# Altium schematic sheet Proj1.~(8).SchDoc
size A4
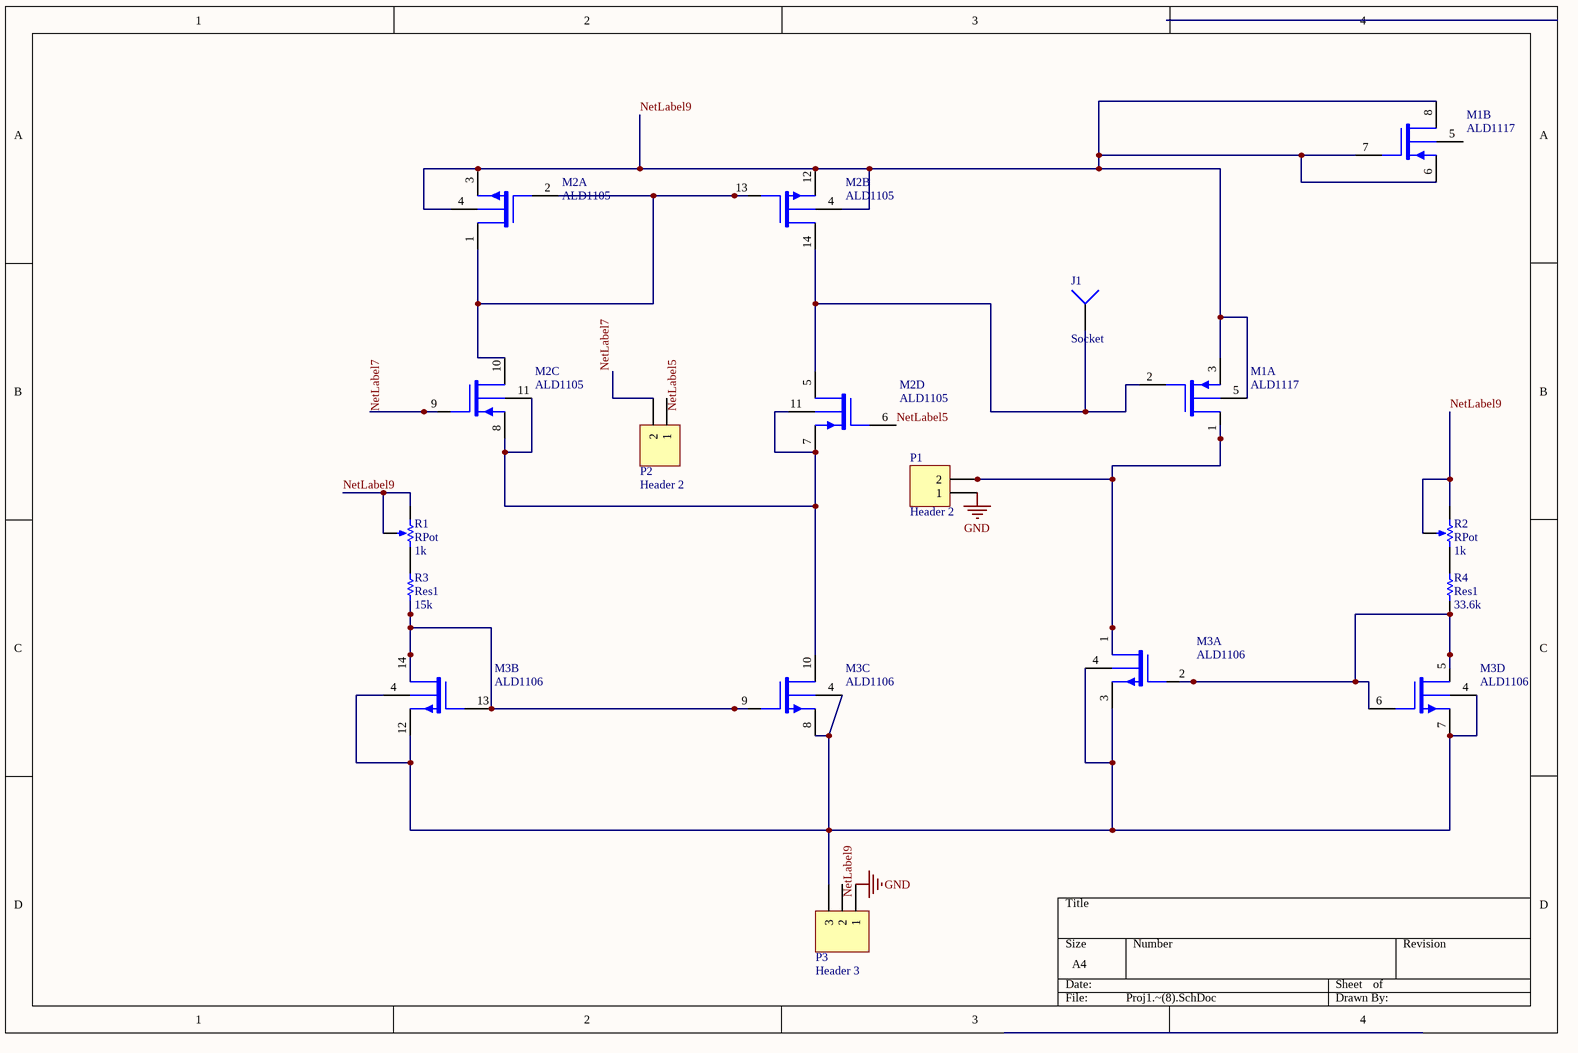
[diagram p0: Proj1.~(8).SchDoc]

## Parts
J1  Socket  [PIN1]
M1  ALD1117  [DIP-8]  (parts A,B of 2)
M2  ALD1105  [DIP-14]  (parts A,B,C,D of 4)
M3  ALD1106  [DIP-14]  (parts A,B,C,D of 4)
P1  Header 2  [HDR1X2]
P2  Header 2  [HDR1X2]
P3  Header 3  [HDR1X3]
R1  RPot  value 1k  [VR5]
R2  RPot  value 1k  [VR5]
R3  Res1  value 15k  [AXIAL-0.3]
R4  Res1  value 33.6k  [AXIAL-0.3]

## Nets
GND: P1.1 P3.1
NetLabel5: M2.6(GP1)
NetLabel7: M2.9(GP2) P2.2
NetLabel9: M1.3(SP1) M1.5(V+) M1.6(SP2) M1.7(GP2) M1.8(DP2) M2.3(SN1) M2.4(V-) M2.12(SN2) R1.1(TOP) R1.2(TAP) R2.1(TOP) R2.2(TAP)
NetJ1_1: J1.1 M1.2(GP1) M2.5(DP1) M2.14(DN2)
NetM1_1: M1.1(DP1) M3.1(DN1) P1.2
NetM2_1: M2.1(DN1) M2.2(GN1) M2.10(DP2) M2.13(GN2)
NetM2_7: M2.7(SP1) M2.8(SP2) M2.11(V+) M3.10(DN3)
NetM3_2: M3.2(GN1) M3.5(DN4) M3.6(GN4) R4.1
NetM3_3: M3.3(SN1) M3.4(V-) M3.7(SN4) M3.8(SN3) M3.12(SN2) P3.3
NetM3_9: M3.9(GN3) M3.13(GN2) M3.14(DN2) R3.1
NetR1_3: R1.3(BOT) R3.2
NetR2_3: R2.3(BOT) R4.2

Not connected (* = marked no-connect by the designer): P2 1; P3 2

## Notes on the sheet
- Labels drawn without touching a wire or pin: NetLabel5, NetLabel9

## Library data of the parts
M1 = ALD1117: Dual P-channel matched MOSFET array
M2 = ALD1105: Dual P-channel and dual N-channel matched MOSFET array
M3 = ALD1106: Quad N-channel matched MOSFET array
P1 P2 = Header 2: Header, 2-Pin
P3 = Header 3: Header, 3-Pin
R1 R2 = RPot: Potentiometer; Sim Note: Enter the Resistance value and the set point into parameter fields.; Set Position: 0.5
R3 R4 = Res1: Resistor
